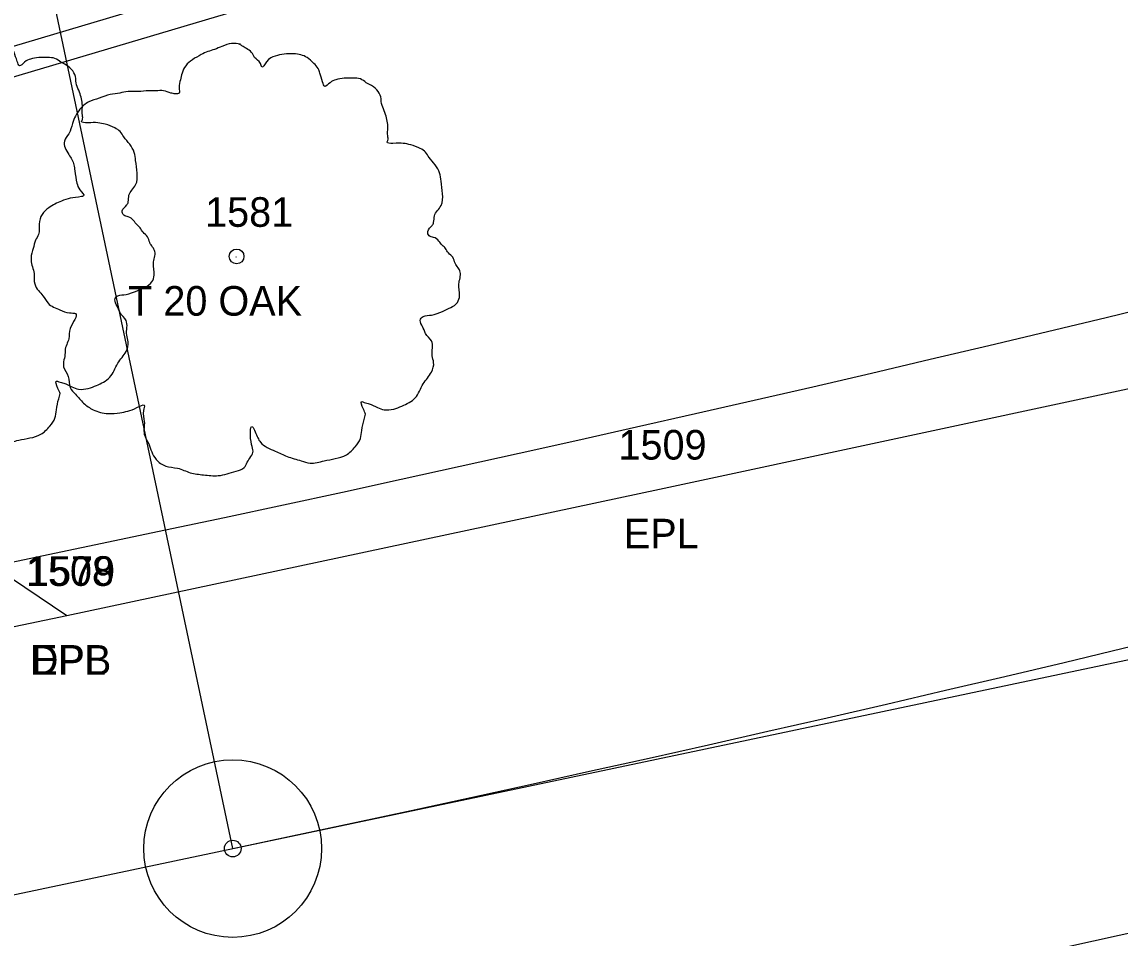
# Model space of a CAD drawing. Extents: x 1964982 to 1970452, y 1116335 to 1119906.
# Drawn here: x 1966603.01 to 1966640.09, y 1117403.17 to 1117434.1 of the extents above; entities that cross this region are included whole.
import ezdxf

# ---------------------------------------------------------------- set-up
doc = ezdxf.new("R2010")
doc.units = 0
for name, color, linetype in [('RD_EX_Driveway', 7, 'Continuous'), ('RD_EX_Driveway_txCode', 7, 'Continuous'), ('RD_EX_DV_Prop', 7, 'Continuous'), ('RD_EX_Road', 7, 'Continuous'), ('RD_EX_Road_txCode', 7, 'Continuous'), ('RD_EX_RW', 7, 'Continuous'), ('RD_EX_VEG', 7, 'Continuous'), ('RD_EX_VEG_txCode', 7, 'Continuous'), ('RD_HC_CL', 7, 'Continuous'), ('RD_HC_CL_Rel', 7, 'Continuous'), ('RD_HC_Data_Rel', 7, 'Continuous'), ('RD_PD_CstnLmt', 7, 'Continuous'), ('RD_PD_Final_TrvlWay', 7, 'Continuous'), ('RD_PD_RW', 7, 'Continuous'), ('RD_SMD_Locator', 7, 'Continuous')]:
    doc.layers.add(name, color=color, linetype=linetype)

msp = doc.modelspace()

# ---------------------------------------------------------------- linework, layer by layer
at = {"layer": 'RD_EX_Driveway'}
msp.add_lwpolyline([(1966578.388, 1117408.593), (1966578.939, 1117419.648), (1966578.028, 1117435.239), (1966589.341, 1117436.481), (1966594.391, 1117424.44), (1966597.459, 1117418.815), (1966604.527, 1117414.058)], dxfattribs=at)
at = {"layer": 'RD_EX_DV_Prop'}
msp.add_line((1966425.261, 1117367.215), (1966684.872, 1117421.945), dxfattribs=at)
at = {"layer": 'RD_EX_Road'}
for points in [[(1966297.245, 1117343.102), (1966344.085, 1117357.038), (1966390.785, 1117368.561), (1966438.122, 1117379.082), (1966484.547, 1117389.131), (1966531.199, 1117398.733), (1966578.388, 1117408.593), (1966604.527, 1117414.058), (1966624.537, 1117418.323), (1966671.319, 1117428.348), (1966716.506, 1117439.32), (1966736.604, 1117445.59), (1966754.133, 1117451.442), (1966759.658, 1117453.517), (1966769.512, 1117457.475)], [(1965729.992, 1117080.297), (1965819.77, 1117119.134), (1965907.737, 1117159.312), (1965995.365, 1117199.039), (1966039.268, 1117218.497), (1966081.241, 1117237.148), (1966124.665, 1117256.555), (1966167.659, 1117275.555), (1966211.467, 1117293.627), (1966257.791, 1117311.581), (1966302.7, 1117327.207), (1966347.903, 1117339.982), (1966394.806, 1117351.637), (1966441.557, 1117361.865), (1966488.625, 1117372.057), (1966534.906, 1117381.34), (1966581.234, 1117390.947), (1966629.533, 1117400.947), (1966675.632, 1117411.107), (1966721.676, 1117422.847), (1966766.802, 1117438.972), (1966775.751, 1117440.571)]]:
    msp.add_lwpolyline(points, dxfattribs=at)
at = {"layer": 'RD_EX_RW'}
for points in [[(1966297.245, 1117343.102), (1966344.085, 1117357.038), (1966390.785, 1117368.561), (1966438.122, 1117379.082), (1966484.547, 1117389.131), (1966531.199, 1117398.733), (1966578.388, 1117408.593), (1966604.527, 1117414.058), (1966624.537, 1117418.323), (1966671.319, 1117428.348), (1966716.506, 1117439.32), (1966736.604, 1117445.59), (1966754.133, 1117451.442), (1966759.658, 1117453.517), (1966769.512, 1117457.475)], [(1965729.992, 1117080.297), (1965819.77, 1117119.134), (1965907.737, 1117159.312), (1965995.365, 1117199.039), (1966039.268, 1117218.497), (1966081.241, 1117237.148), (1966124.665, 1117256.555), (1966167.659, 1117275.555), (1966211.467, 1117293.627), (1966257.791, 1117311.581), (1966302.7, 1117327.207), (1966347.903, 1117339.982), (1966394.806, 1117351.637), (1966441.557, 1117361.865), (1966488.625, 1117372.057), (1966534.906, 1117381.34), (1966581.234, 1117390.947), (1966629.533, 1117400.947), (1966675.632, 1117411.107), (1966721.676, 1117422.847), (1966766.802, 1117438.972), (1966775.751, 1117440.571)]]:
    msp.add_lwpolyline(points, dxfattribs=at)
at = {"layer": 'RD_EX_VEG'}
for centre, radius in [((1966610.256, 1117426.183), 0.25), ((1966610.256, 1117426.183), 0.25), ((1966610.244, 1117426.164), 0.0001), ((1966610.244, 1117426.164), 0.0001)]:
    msp.add_circle(centre, radius, dxfattribs=at)
for points in [[(1966600.075, 1117434.046), (1966599.776, 1117434.071), (1966599.451, 1117433.971), (1966599.201, 1117433.871), (1966598.976, 1117433.796), (1966598.751, 1117433.696), (1966598.451, 1117433.521), (1966598.226, 1117433.321), (1966598.101, 1117433.071), (1966598.051, 1117432.846), (1966598.001, 1117432.571), (1966598.001, 1117432.396), (1966597.876, 1117432.371), (1966597.726, 1117432.396), (1966597.477, 1117432.471), (1966597.227, 1117432.471), (1966596.977, 1117432.471), (1966596.627, 1117432.446), (1966596.277, 1117432.446), (1966596.002, 1117432.396), (1966595.677, 1117432.346), (1966595.303, 1117432.221), (1966594.953, 1117432.096), (1966594.653, 1117431.847), (1966594.403, 1117431.372), (1966594.278, 1117431.022), (1966594.128, 1117430.772), (1966594.278, 1117430.322), (1966594.453, 1117429.972), (1966594.478, 1117429.772), (1966594.553, 1117429.348), (1966594.653, 1117429.123), (1966594.778, 1117428.923), (1966594.703, 1117428.898), (1966594.328, 1117428.848), (1966594.028, 1117428.748), (1966593.603, 1117428.523), (1966593.378, 1117428.298), (1966593.278, 1117427.973), (1966593.253, 1117427.623), (1966593.154, 1117427.424), (1966593.079, 1117427.149), (1966593.054, 1117427.074), (1966593.004, 1117426.749), (1966593.104, 1117426.299), (1966593.129, 1117425.949), (1966593.253, 1117425.724), (1966593.403, 1117425.549), (1966593.578, 1117425.299), (1966593.978, 1117425.075), (1966594.303, 1117424.975), (1966594.503, 1117424.95), (1966594.328, 1117424.45), (1966594.278, 1117424.1), (1966594.153, 1117423.7), (1966594.153, 1117423.625), (1966594.103, 1117423.15), (1966594.253, 1117422.825), (1966594.328, 1117422.451), (1966594.503, 1117422.226), (1966594.778, 1117421.926), (1966595.103, 1117421.701), (1966595.602, 1117421.576), (1966596.002, 1117421.601), (1966596.577, 1117421.776), (1966596.827, 1117421.851), (1966596.802, 1117421.676), (1966596.827, 1117421.301), (1966596.827, 1117420.876), (1966596.977, 1117420.552), (1966597.077, 1117420.277), (1966597.227, 1117420.027), (1966597.552, 1117419.802), (1966597.951, 1117419.727), (1966598.376, 1117419.577), (1966598.826, 1117419.502), (1966599.326, 1117419.477), (1966599.926, 1117419.627), (1966600.2, 1117419.752), (1966600.3, 1117419.927), (1966600.5, 1117420.302), (1966600.45, 1117420.527), (1966600.475, 1117421.126), (1966600.575, 1117420.951), (1966600.75, 1117420.601), (1966601.25, 1117420.302), (1966601.65, 1117420.127), (1966602.125, 1117419.977), (1966602.424, 1117419.902), (1966602.899, 1117419.977), (1966603.274, 1117420.052), (1966603.649, 1117420.177), (1966603.949, 1117420.452), (1966604.124, 1117420.726), (1966604.174, 1117421.001), (1966604.249, 1117421.376), (1966604.299, 1117421.551)], [(1966600.075, 1117434.046), (1966599.776, 1117434.071), (1966599.451, 1117433.971), (1966599.201, 1117433.871), (1966598.976, 1117433.796), (1966598.751, 1117433.696), (1966598.451, 1117433.521), (1966598.226, 1117433.321), (1966598.101, 1117433.071), (1966598.051, 1117432.846), (1966598.001, 1117432.571), (1966598.001, 1117432.396), (1966597.876, 1117432.371), (1966597.726, 1117432.396), (1966597.477, 1117432.471), (1966597.227, 1117432.471), (1966596.977, 1117432.471), (1966596.627, 1117432.446), (1966596.277, 1117432.446), (1966596.002, 1117432.396), (1966595.677, 1117432.346), (1966595.303, 1117432.221), (1966594.953, 1117432.096), (1966594.653, 1117431.847), (1966594.403, 1117431.372), (1966594.278, 1117431.022), (1966594.128, 1117430.772), (1966594.278, 1117430.322), (1966594.453, 1117429.972), (1966594.478, 1117429.772), (1966594.553, 1117429.348), (1966594.653, 1117429.123), (1966594.778, 1117428.923), (1966594.703, 1117428.898), (1966594.328, 1117428.848), (1966594.028, 1117428.748), (1966593.603, 1117428.523), (1966593.378, 1117428.298), (1966593.278, 1117427.973), (1966593.253, 1117427.623), (1966593.154, 1117427.424), (1966593.079, 1117427.149), (1966593.054, 1117427.074), (1966593.004, 1117426.749), (1966593.104, 1117426.299), (1966593.129, 1117425.949), (1966593.253, 1117425.724), (1966593.403, 1117425.549), (1966593.578, 1117425.299), (1966593.978, 1117425.075), (1966594.303, 1117424.975), (1966594.503, 1117424.95), (1966594.328, 1117424.45), (1966594.278, 1117424.1), (1966594.153, 1117423.7), (1966594.153, 1117423.625), (1966594.103, 1117423.15), (1966594.253, 1117422.825), (1966594.328, 1117422.451), (1966594.503, 1117422.226), (1966594.778, 1117421.926), (1966595.103, 1117421.701), (1966595.602, 1117421.576), (1966596.002, 1117421.601), (1966596.577, 1117421.776), (1966596.827, 1117421.851), (1966596.802, 1117421.676), (1966596.827, 1117421.301), (1966596.827, 1117420.876), (1966596.977, 1117420.552), (1966597.077, 1117420.277), (1966597.227, 1117420.027), (1966597.552, 1117419.802), (1966597.951, 1117419.727), (1966598.376, 1117419.577), (1966598.826, 1117419.502), (1966599.326, 1117419.477), (1966599.926, 1117419.627), (1966600.2, 1117419.752), (1966600.3, 1117419.927), (1966600.5, 1117420.302), (1966600.45, 1117420.527), (1966600.475, 1117421.126), (1966600.575, 1117420.951), (1966600.75, 1117420.601), (1966601.25, 1117420.302), (1966601.65, 1117420.127), (1966602.125, 1117419.977), (1966602.424, 1117419.902), (1966602.899, 1117419.977), (1966603.274, 1117420.052), (1966603.649, 1117420.177), (1966603.949, 1117420.452), (1966604.124, 1117420.726), (1966604.174, 1117421.001), (1966604.249, 1117421.376), (1966604.299, 1117421.551)], [(1966604.299, 1117421.551), (1966604.224, 1117421.726), (1966604.174, 1117421.976), (1966604.249, 1117421.951), (1966604.424, 1117421.901), (1966604.698, 1117421.776), (1966604.923, 1117421.701), (1966605.248, 1117421.726), (1966605.523, 1117421.826), (1966605.973, 1117422.101), (1966606.248, 1117422.576), (1966606.523, 1117422.975), (1966606.598, 1117423.3), (1966606.548, 1117423.525), (1966606.523, 1117424.025), (1966606.323, 1117424.275), (1966606.273, 1117424.4), (1966606.173, 1117424.8), (1966606.248, 1117424.85), (1966606.523, 1117424.9), (1966606.897, 1117425.025), (1966607.172, 1117425.149), (1966607.397, 1117425.324), (1966607.472, 1117425.549), (1966607.447, 1117425.949), (1966607.497, 1117426.349), (1966607.422, 1117426.499), (1966607.322, 1117426.649), (1966607.247, 1117426.849), (1966607.097, 1117426.999), (1966606.997, 1117427.149), (1966606.897, 1117427.249), (1966606.773, 1117427.399), (1966606.598, 1117427.523), (1966606.448, 1117427.573), (1966606.398, 1117427.723), (1966606.548, 1117427.923), (1966606.598, 1117428.023), (1966606.623, 1117428.248), (1966606.848, 1117428.598), (1966606.897, 1117428.998), (1966606.848, 1117429.423), (1966606.798, 1117429.698), (1966606.648, 1117429.972), (1966606.448, 1117430.222), (1966606.323, 1117430.397), (1966606.148, 1117430.522), (1966605.823, 1117430.647), (1966605.573, 1117430.697), (1966605.223, 1117430.697), (1966605.023, 1117430.747), (1966605.048, 1117430.797), (1966605.048, 1117430.947), (1966605.048, 1117431.222), (1966604.973, 1117431.672), (1966604.823, 1117432.171), (1966604.823, 1117432.196), (1966604.723, 1117432.446), (1966604.499, 1117432.646), (1966604.324, 1117432.746), (1966604.124, 1117432.871), (1966603.874, 1117432.896), (1966603.574, 1117432.896), (1966603.299, 1117432.846), (1966603.099, 1117432.746), (1966602.924, 1117432.621), (1966602.849, 1117432.771), (1966602.749, 1117433.071), (1966602.699, 1117433.221), (1966602.549, 1117433.396), (1966602.325, 1117433.596), (1966601.875, 1117433.721), (1966601.25, 1117433.646), (1966600.95, 1117433.446), (1966600.8, 1117433.271), (1966600.75, 1117433.396), (1966600.55, 1117433.596), (1966600.45, 1117433.771), (1966600.275, 1117433.896), (1966600.125, 1117433.996), (1966600.025, 1117434.046)], [(1966604.299, 1117421.551), (1966604.224, 1117421.726), (1966604.174, 1117421.976), (1966604.249, 1117421.951), (1966604.424, 1117421.901), (1966604.698, 1117421.776), (1966604.923, 1117421.701), (1966605.248, 1117421.726), (1966605.523, 1117421.826), (1966605.973, 1117422.101), (1966606.248, 1117422.576), (1966606.523, 1117422.975), (1966606.598, 1117423.3), (1966606.548, 1117423.525), (1966606.523, 1117424.025), (1966606.323, 1117424.275), (1966606.273, 1117424.4), (1966606.173, 1117424.8), (1966606.248, 1117424.85), (1966606.523, 1117424.9), (1966606.897, 1117425.025), (1966607.172, 1117425.149), (1966607.397, 1117425.324), (1966607.472, 1117425.549), (1966607.447, 1117425.949), (1966607.497, 1117426.349), (1966607.422, 1117426.499), (1966607.322, 1117426.649), (1966607.247, 1117426.849), (1966607.097, 1117426.999), (1966606.997, 1117427.149), (1966606.897, 1117427.249), (1966606.773, 1117427.399), (1966606.598, 1117427.523), (1966606.448, 1117427.573), (1966606.398, 1117427.723), (1966606.548, 1117427.923), (1966606.598, 1117428.023), (1966606.623, 1117428.248), (1966606.848, 1117428.598), (1966606.897, 1117428.998), (1966606.848, 1117429.423), (1966606.798, 1117429.698), (1966606.648, 1117429.972), (1966606.448, 1117430.222), (1966606.323, 1117430.397), (1966606.148, 1117430.522), (1966605.823, 1117430.647), (1966605.573, 1117430.697), (1966605.223, 1117430.697), (1966605.023, 1117430.747), (1966605.048, 1117430.797), (1966605.048, 1117430.947), (1966605.048, 1117431.222), (1966604.973, 1117431.672), (1966604.823, 1117432.171), (1966604.823, 1117432.196), (1966604.723, 1117432.446), (1966604.499, 1117432.646), (1966604.324, 1117432.746), (1966604.124, 1117432.871), (1966603.874, 1117432.896), (1966603.574, 1117432.896), (1966603.299, 1117432.846), (1966603.099, 1117432.746), (1966602.924, 1117432.621), (1966602.849, 1117432.771), (1966602.749, 1117433.071), (1966602.699, 1117433.221), (1966602.549, 1117433.396), (1966602.325, 1117433.596), (1966601.875, 1117433.721), (1966601.25, 1117433.646), (1966600.95, 1117433.446), (1966600.8, 1117433.271), (1966600.75, 1117433.396), (1966600.55, 1117433.596), (1966600.45, 1117433.771), (1966600.275, 1117433.896), (1966600.125, 1117433.996), (1966600.025, 1117434.046)], [(1966610.388, 1117433.35), (1966610.088, 1117433.375), (1966609.763, 1117433.275), (1966609.514, 1117433.175), (1966609.289, 1117433.1), (1966609.064, 1117433), (1966608.764, 1117432.825), (1966608.539, 1117432.625), (1966608.414, 1117432.375), (1966608.364, 1117432.151), (1966608.314, 1117431.876), (1966608.314, 1117431.701), (1966608.189, 1117431.676), (1966608.039, 1117431.701), (1966607.789, 1117431.776), (1966607.539, 1117431.776), (1966607.289, 1117431.776), (1966606.94, 1117431.751), (1966606.59, 1117431.751), (1966606.315, 1117431.701), (1966605.99, 1117431.651), (1966605.615, 1117431.526), (1966605.265, 1117431.401), (1966604.966, 1117431.151), (1966604.716, 1117430.676), (1966604.591, 1117430.326), (1966604.441, 1117430.076), (1966604.591, 1117429.627), (1966604.766, 1117429.277), (1966604.791, 1117429.077), (1966604.866, 1117428.652), (1966604.966, 1117428.427), (1966605.09, 1117428.227), (1966605.016, 1117428.202), (1966604.641, 1117428.152), (1966604.341, 1117428.052), (1966603.916, 1117427.827), (1966603.691, 1117427.603), (1966603.591, 1117427.278), (1966603.566, 1117426.928), (1966603.466, 1117426.728), (1966603.391, 1117426.453), (1966603.366, 1117426.378), (1966603.316, 1117426.053), (1966603.416, 1117425.603), (1966603.441, 1117425.254), (1966603.566, 1117425.029), (1966603.716, 1117424.854), (1966603.891, 1117424.604), (1966604.291, 1117424.379), (1966604.616, 1117424.279), (1966604.816, 1117424.254), (1966604.641, 1117423.754), (1966604.591, 1117423.404), (1966604.466, 1117423.005), (1966604.466, 1117422.93), (1966604.416, 1117422.455), (1966604.566, 1117422.13), (1966604.641, 1117421.755), (1966604.816, 1117421.53), (1966605.09, 1117421.23), (1966605.415, 1117421.005), (1966605.915, 1117420.88), (1966606.315, 1117420.905), (1966606.89, 1117421.08), (1966607.14, 1117421.155), (1966607.115, 1117420.98), (1966607.14, 1117420.606), (1966607.14, 1117420.181), (1966607.289, 1117419.856), (1966607.389, 1117419.581), (1966607.539, 1117419.331), (1966607.864, 1117419.106), (1966608.264, 1117419.031), (1966608.689, 1117418.881), (1966609.139, 1117418.806), (1966609.638, 1117418.781), (1966610.238, 1117418.931), (1966610.513, 1117419.056), (1966610.613, 1117419.231), (1966610.813, 1117419.606), (1966610.763, 1117419.831), (1966610.788, 1117420.431), (1966610.888, 1117420.256), (1966611.063, 1117419.906), (1966611.563, 1117419.606), (1966611.962, 1117419.431), (1966612.437, 1117419.281), (1966612.737, 1117419.206), (1966613.212, 1117419.281), (1966613.587, 1117419.356), (1966613.962, 1117419.481), (1966614.261, 1117419.756), (1966614.436, 1117420.031), (1966614.486, 1117420.306), (1966614.561, 1117420.681), (1966614.611, 1117420.855)], [(1966610.388, 1117433.35), (1966610.088, 1117433.375), (1966609.763, 1117433.275), (1966609.514, 1117433.175), (1966609.289, 1117433.1), (1966609.064, 1117433), (1966608.764, 1117432.825), (1966608.539, 1117432.625), (1966608.414, 1117432.375), (1966608.364, 1117432.151), (1966608.314, 1117431.876), (1966608.314, 1117431.701), (1966608.189, 1117431.676), (1966608.039, 1117431.701), (1966607.789, 1117431.776), (1966607.539, 1117431.776), (1966607.289, 1117431.776), (1966606.94, 1117431.751), (1966606.59, 1117431.751), (1966606.315, 1117431.701), (1966605.99, 1117431.651), (1966605.615, 1117431.526), (1966605.265, 1117431.401), (1966604.966, 1117431.151), (1966604.716, 1117430.676), (1966604.591, 1117430.326), (1966604.441, 1117430.076), (1966604.591, 1117429.627), (1966604.766, 1117429.277), (1966604.791, 1117429.077), (1966604.866, 1117428.652), (1966604.966, 1117428.427), (1966605.09, 1117428.227), (1966605.016, 1117428.202), (1966604.641, 1117428.152), (1966604.341, 1117428.052), (1966603.916, 1117427.827), (1966603.691, 1117427.603), (1966603.591, 1117427.278), (1966603.566, 1117426.928), (1966603.466, 1117426.728), (1966603.391, 1117426.453), (1966603.366, 1117426.378), (1966603.316, 1117426.053), (1966603.416, 1117425.603), (1966603.441, 1117425.254), (1966603.566, 1117425.029), (1966603.716, 1117424.854), (1966603.891, 1117424.604), (1966604.291, 1117424.379), (1966604.616, 1117424.279), (1966604.816, 1117424.254), (1966604.641, 1117423.754), (1966604.591, 1117423.404), (1966604.466, 1117423.005), (1966604.466, 1117422.93), (1966604.416, 1117422.455), (1966604.566, 1117422.13), (1966604.641, 1117421.755), (1966604.816, 1117421.53), (1966605.09, 1117421.23), (1966605.415, 1117421.005), (1966605.915, 1117420.88), (1966606.315, 1117420.905), (1966606.89, 1117421.08), (1966607.14, 1117421.155), (1966607.115, 1117420.98), (1966607.14, 1117420.606), (1966607.14, 1117420.181), (1966607.289, 1117419.856), (1966607.389, 1117419.581), (1966607.539, 1117419.331), (1966607.864, 1117419.106), (1966608.264, 1117419.031), (1966608.689, 1117418.881), (1966609.139, 1117418.806), (1966609.638, 1117418.781), (1966610.238, 1117418.931), (1966610.513, 1117419.056), (1966610.613, 1117419.231), (1966610.813, 1117419.606), (1966610.763, 1117419.831), (1966610.788, 1117420.431), (1966610.888, 1117420.256), (1966611.063, 1117419.906), (1966611.563, 1117419.606), (1966611.962, 1117419.431), (1966612.437, 1117419.281), (1966612.737, 1117419.206), (1966613.212, 1117419.281), (1966613.587, 1117419.356), (1966613.962, 1117419.481), (1966614.261, 1117419.756), (1966614.436, 1117420.031), (1966614.486, 1117420.306), (1966614.561, 1117420.681), (1966614.611, 1117420.855)], [(1966614.611, 1117420.855), (1966614.536, 1117421.03), (1966614.486, 1117421.28), (1966614.561, 1117421.255), (1966614.736, 1117421.205), (1966615.011, 1117421.08), (1966615.236, 1117421.005), (1966615.561, 1117421.03), (1966615.836, 1117421.13), (1966616.286, 1117421.405), (1966616.56, 1117421.88), (1966616.835, 1117422.28), (1966616.91, 1117422.605), (1966616.86, 1117422.83), (1966616.835, 1117423.329), (1966616.635, 1117423.579), (1966616.585, 1117423.704), (1966616.485, 1117424.104), (1966616.56, 1117424.154), (1966616.835, 1117424.204), (1966617.21, 1117424.329), (1966617.485, 1117424.454), (1966617.71, 1117424.629), (1966617.785, 1117424.854), (1966617.76, 1117425.254), (1966617.81, 1117425.653), (1966617.735, 1117425.803), (1966617.635, 1117425.953), (1966617.56, 1117426.153), (1966617.41, 1117426.303), (1966617.31, 1117426.453), (1966617.21, 1117426.553), (1966617.085, 1117426.703), (1966616.91, 1117426.828), (1966616.76, 1117426.878), (1966616.71, 1117427.028), (1966616.86, 1117427.228), (1966616.91, 1117427.328), (1966616.935, 1117427.553), (1966617.16, 1117427.902), (1966617.21, 1117428.302), (1966617.16, 1117428.727), (1966617.11, 1117429.002), (1966616.96, 1117429.277), (1966616.76, 1117429.527), (1966616.635, 1117429.702), (1966616.46, 1117429.827), (1966616.136, 1117429.952), (1966615.886, 1117430.001), (1966615.536, 1117430.001), (1966615.336, 1117430.051), (1966615.361, 1117430.101), (1966615.361, 1117430.251), (1966615.361, 1117430.526), (1966615.286, 1117430.976), (1966615.136, 1117431.476), (1966615.136, 1117431.501), (1966615.036, 1117431.751), (1966614.811, 1117431.951), (1966614.636, 1117432.051), (1966614.436, 1117432.176), (1966614.186, 1117432.201), (1966613.887, 1117432.201), (1966613.612, 1117432.151), (1966613.412, 1117432.051), (1966613.237, 1117431.926), (1966613.162, 1117432.076), (1966613.062, 1117432.375), (1966613.012, 1117432.525), (1966612.862, 1117432.7), (1966612.637, 1117432.9), (1966612.187, 1117433.025), (1966611.563, 1117432.95), (1966611.263, 1117432.75), (1966611.113, 1117432.575), (1966611.063, 1117432.7), (1966610.863, 1117432.9), (1966610.763, 1117433.075), (1966610.588, 1117433.2), (1966610.438, 1117433.3), (1966610.338, 1117433.35)], [(1966614.611, 1117420.855), (1966614.536, 1117421.03), (1966614.486, 1117421.28), (1966614.561, 1117421.255), (1966614.736, 1117421.205), (1966615.011, 1117421.08), (1966615.236, 1117421.005), (1966615.561, 1117421.03), (1966615.836, 1117421.13), (1966616.286, 1117421.405), (1966616.56, 1117421.88), (1966616.835, 1117422.28), (1966616.91, 1117422.605), (1966616.86, 1117422.83), (1966616.835, 1117423.329), (1966616.635, 1117423.579), (1966616.585, 1117423.704), (1966616.485, 1117424.104), (1966616.56, 1117424.154), (1966616.835, 1117424.204), (1966617.21, 1117424.329), (1966617.485, 1117424.454), (1966617.71, 1117424.629), (1966617.785, 1117424.854), (1966617.76, 1117425.254), (1966617.81, 1117425.653), (1966617.735, 1117425.803), (1966617.635, 1117425.953), (1966617.56, 1117426.153), (1966617.41, 1117426.303), (1966617.31, 1117426.453), (1966617.21, 1117426.553), (1966617.085, 1117426.703), (1966616.91, 1117426.828), (1966616.76, 1117426.878), (1966616.71, 1117427.028), (1966616.86, 1117427.228), (1966616.91, 1117427.328), (1966616.935, 1117427.553), (1966617.16, 1117427.902), (1966617.21, 1117428.302), (1966617.16, 1117428.727), (1966617.11, 1117429.002), (1966616.96, 1117429.277), (1966616.76, 1117429.527), (1966616.635, 1117429.702), (1966616.46, 1117429.827), (1966616.136, 1117429.952), (1966615.886, 1117430.001), (1966615.536, 1117430.001), (1966615.336, 1117430.051), (1966615.361, 1117430.101), (1966615.361, 1117430.251), (1966615.361, 1117430.526), (1966615.286, 1117430.976), (1966615.136, 1117431.476), (1966615.136, 1117431.501), (1966615.036, 1117431.751), (1966614.811, 1117431.951), (1966614.636, 1117432.051), (1966614.436, 1117432.176), (1966614.186, 1117432.201), (1966613.887, 1117432.201), (1966613.612, 1117432.151), (1966613.412, 1117432.051), (1966613.237, 1117431.926), (1966613.162, 1117432.076), (1966613.062, 1117432.375), (1966613.012, 1117432.525), (1966612.862, 1117432.7), (1966612.637, 1117432.9), (1966612.187, 1117433.025), (1966611.563, 1117432.95), (1966611.263, 1117432.75), (1966611.113, 1117432.575), (1966611.063, 1117432.7), (1966610.863, 1117432.9), (1966610.763, 1117433.075), (1966610.588, 1117433.2), (1966610.438, 1117433.3), (1966610.338, 1117433.35)]]:
    msp.add_spline(points, degree=3, dxfattribs=at)
at = {"layer": 'RD_HC_CL'}
msp.add_line((1966425.261, 1117367.215), (1966684.871, 1117421.945), dxfattribs=at)
at = {"layer": 'RD_HC_CL_Rel'}
msp.add_arc((1966373.74, 1118527.456), 1145.915, 281.904723, 295.046328, dxfattribs=at)
at = {"layer": 'RD_HC_Data_Rel'}
msp.add_line((1966610.125, 1117406.187), (1966579.812, 1117549.972), dxfattribs=at)
for radius in [3, 0.282]:
    msp.add_circle((1966610.125, 1117406.187), radius, dxfattribs=at)
at = {"layer": 'RD_PD_CstnLmt'}
msp.add_line((1966619.782, 1117437.316), (1966572.088, 1117423.122), dxfattribs=at)
at = {"layer": 'RD_PD_Final_TrvlWay'}
msp.add_line((1966422.992, 1117377.978), (1966607.856, 1117416.951), dxfattribs=at)
for radius in [1134.915, 1156.915]:
    msp.add_arc((1966373.74, 1118527.456), radius, 281.904723, 295.046328, dxfattribs=at)
at = {"layer": 'RD_PD_RW'}
msp.add_line((1966619.521, 1117438.281), (1966571.829, 1117424.088), dxfattribs=at)
at = {"layer": 'RD_SMD_Locator'}
for centre in [(1966624.537, 1117418.323), (1966624.537, 1117418.323), (1966604.527, 1117414.058), (1966604.527, 1117414.058), (1966604.527, 1117414.058), (1966604.527, 1117414.058)]:
    msp.add_circle(centre, 0.001, dxfattribs=at)

# ---------------------------------------------------------------- texts
at = {"layer": 'RD_EX_Driveway_txCode'}
for s, p in [('1579', (1966603.181, 1117415.058)), ('1579', (1966603.181, 1117415.058)), ('DPB', (1966603.275, 1117412.058)), ('DPB', (1966603.275, 1117412.058))]:
    msp.add_text(s, height=1, dxfattribs=at).set_placement(p)
at = {"layer": 'RD_EX_Road_txCode'}
for s, p in [('1509', (1966623.151, 1117419.323)), ('1509', (1966623.151, 1117419.323)), ('EPL', (1966623.332, 1117416.323)), ('EPL', (1966623.332, 1117416.323)), ('1508', (1966603.141, 1117415.058)), ('1508', (1966603.141, 1117415.058)), ('EPL', (1966603.322, 1117412.058)), ('EPL', (1966603.322, 1117412.058))]:
    msp.add_text(s, height=1, dxfattribs=at).set_placement(p)
at = {"layer": 'RD_EX_VEG_txCode'}
for s, p in [('1581', (1966609.193, 1117427.183)), ('1581', (1966609.193, 1117427.183)), ('T 20 OAK', (1966606.595, 1117424.183)), ('T 20 OAK', (1966606.595, 1117424.183))]:
    msp.add_text(s, height=1, dxfattribs=at).set_placement(p)

doc.saveas('drawing.dxf')
